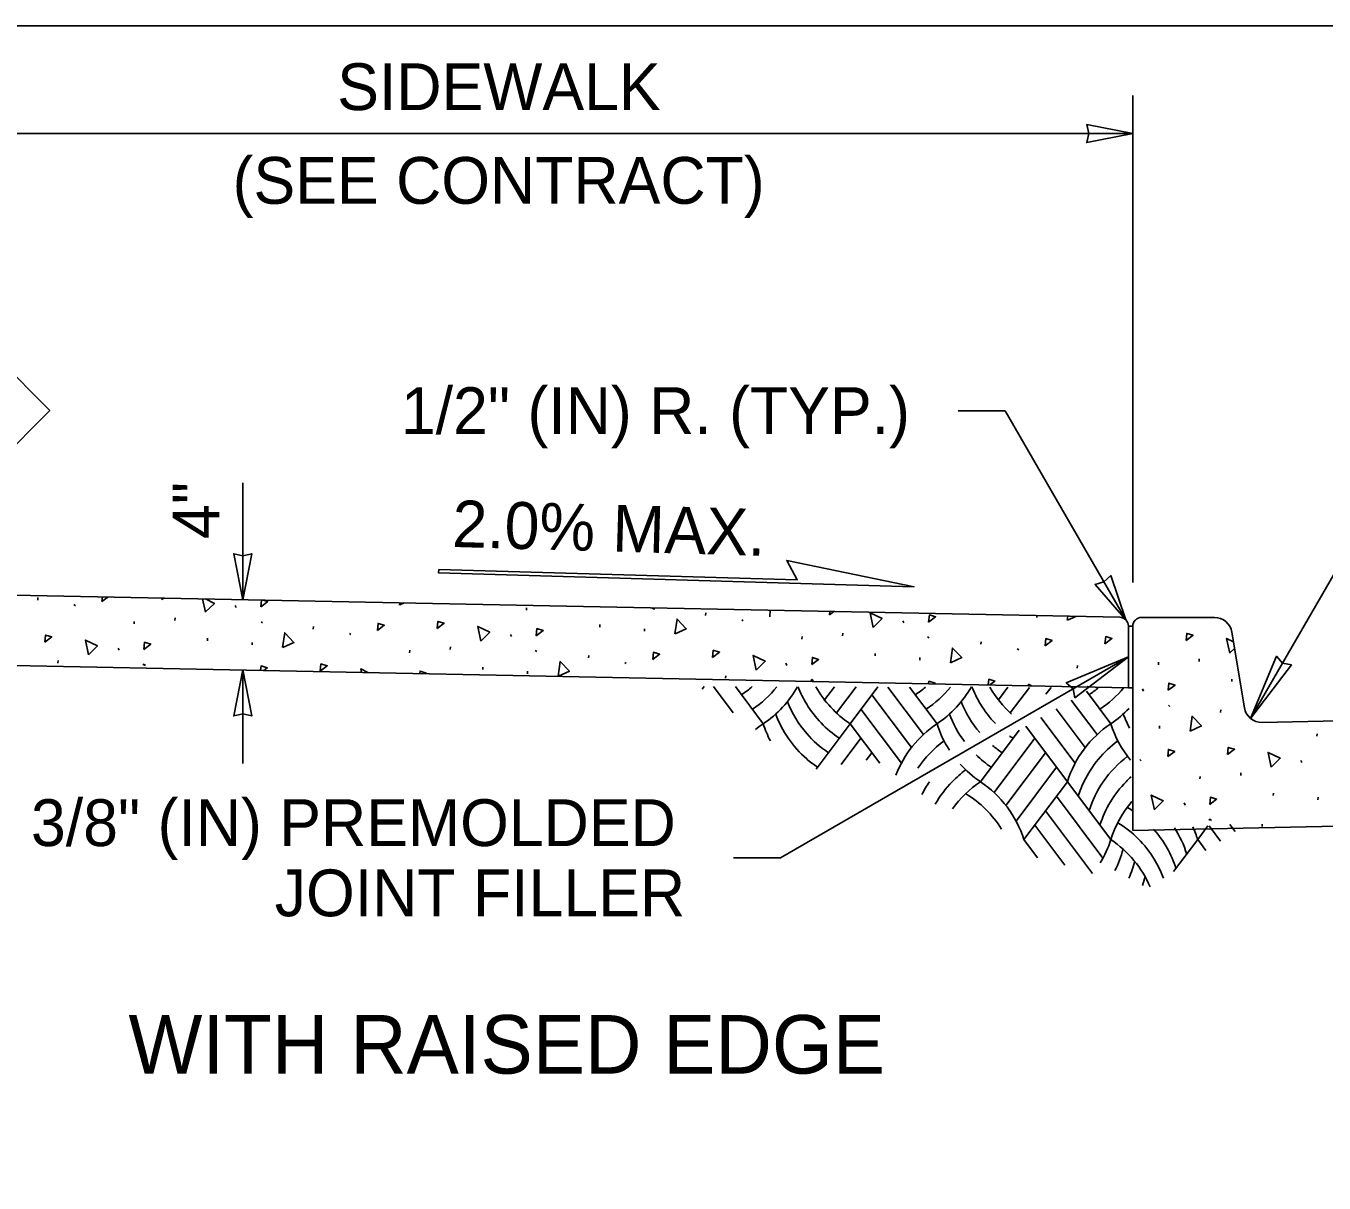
# Model space of a CAD drawing. Extents: x 99862 to 103151, y 100000 to 102076.
# Drawn here: x 100337.6 to 100781.3, y 101680 to 102075.5 of the extents above; entities that cross this region are included whole.
import ezdxf

# ---------------------------------------------------------------- set-up
doc = ezdxf.new("R2010")
doc.units = 0
for name, color, linetype in [('Level 1', 7, 'Continuous'), ('Level 13', 7, 'Continuous'), ('Level 15', 7, 'Continuous'), ('Level 16', 7, 'Continuous'), ('Level 20', 7, 'Continuous'), ('Level 34', 7, 'Continuous'), ('Level 6', 7, 'Continuous')]:
    doc.layers.add(name, color=color, linetype=linetype)

msp = doc.modelspace()

# ---------------------------------------------------------------- linework, layer by layer
at = {"layer": 'Level 1'}
msp.add_lwpolyline([(99862, 99999.5), (103151, 99999.5), (103151, 102075.5), (99862, 102075.5)], close=True, dxfattribs=at)
at = {"layer": 'Level 13'}
for p, q in [((100341.62, 101879.25), (100341.68, 101880.12)), ((100353.99, 101877.7), (100354.51, 101877.32)), ((100409.07, 101877.42), (100409.43, 101876.7)), ((100454.83, 101878.48), (100454.83, 101878.51)), ((100508.65, 101875.77), (100508.71, 101876.64)), ((100522.57, 101876.96), (100522.59, 101877.16)), ((100551.64, 101876.57), (100552.15, 101876.2)), ((100552.04, 101876.51), (100552.55, 101876.13)), ((100374.54, 101871.1), (100374.6, 101871.97)), ((100388.47, 101872.3), (100388.53, 101873.17)), ((100417.93, 101871.84), (100418.45, 101871.46)), ((100569.85, 101874.03), (100569.91, 101874.9)), ((100582.23, 101872.49), (100582.74, 101872.11)), ((100637.31, 101872.21), (100637.67, 101871.49)), ((100683.06, 101873.27), (100683.11, 101873.95)), ((100435.75, 101869.37), (100435.81, 101870.24)), ((100448.12, 101867.82), (100448.64, 101867.44)), ((100503.2, 101867.54), (100503.56, 101866.82)), ((100533.69, 101870.05), (100533.75, 101870.92)), ((100548.96, 101868.6), (100549.02, 101869.47)), ((100616.71, 101867.08), (100616.77, 101867.95)), ((100399.59, 101865.38), (100399.65, 101866.25)), ((100414.86, 101863.93), (100414.92, 101864.81)), ((100482.6, 101862.42), (100482.66, 101863.29)), ((100602.78, 101865.89), (100602.84, 101866.76)), ((100645.76, 101866.7), (100646.28, 101866.32)), ((100663.99, 101864.15), (100664.05, 101865.02)), ((100348.5, 101857.75), (100348.56, 101858.62)), ((100369.1, 101862.87), (100369.46, 101862.15)), ((100468.67, 101861.22), (100468.73, 101862.09)), ((100511.66, 101862.03), (100512.18, 101861.65)), ((100529.88, 101859.48), (100529.94, 101860.36)), ((100627.82, 101860.17), (100627.88, 101861.04)), ((100643.09, 101858.72), (100643.15, 101859.59)), ((100676.36, 101862.61), (100676.88, 101862.23)), ((100738.57, 101858.31), (100738.63, 101859.18)), ((100377.56, 101857.36), (100378.07, 101856.98)), ((100377.96, 101857.29), (100378.48, 101856.92)), ((100493.72, 101855.5), (100493.78, 101856.37)), ((100508.99, 101854.05), (100509.05, 101854.92)), ((100542.26, 101857.94), (100542.77, 101857.56)), ((100597.34, 101857.66), (100597.69, 101856.94)), ((100696.91, 101856), (100696.97, 101856.88)), ((100710.84, 101857.2), (100710.9, 101858.07)), ((100724.64, 101857.12), (100724.7, 101857.99)), ((100576.73, 101852.53), (100576.79, 101853.41)), ((100605.79, 101852.15), (100606.31, 101851.77)), ((100606.2, 101852.08), (100606.71, 101851.7)), ((100749.69, 101851.4), (100749.75, 101852.27)), ((100719.2, 101848.89), (100719.56, 101848.17)), ((100728.06, 101843.31), (100728.58, 101842.93)), ((100745.88, 101840.83), (100745.94, 101841.7)), ((100724.99, 101835.4), (100725.05, 101836.27)), ((100778.8, 101832.69), (100778.86, 101833.56)), ((100718.28, 101824.74), (100718.8, 101824.36)), ((100773.36, 101824.46), (100773.72, 101823.74)), ((100738.83, 101818.14), (100738.89, 101819.01)), ((100752.76, 101819.33), (100752.82, 101820.2)), ((100733.39, 101809.91), (100733.75, 101809.19)), ((100763.88, 101812.42), (100763.94, 101813.29)), ((100779.15, 101810.97), (100779.21, 101811.84)), ((100741.85, 101804.4), (100742.36, 101804.02)), ((100742.25, 101804.33), (100742.77, 101803.95)), ((100760.07, 101801.85), (100760.13, 101802.72))]:
    msp.add_line(p, q, dxfattribs=at)
for points in [[(100363.54, 101878.72), (100363.7, 101880.33)], [(100365.6, 101880.3), (100363.54, 101878.72)], [(100384.01, 101879.42), (100384.06, 101879.93)], [(100384.66, 101879.91), (100384.01, 101879.42)], [(100398.94, 101875.13), (100397.97, 101879.65)], [(100398.91, 101879.63), (100401.97, 101878.14), (100399, 101875.19)], [(100417.87, 101876.95), (100418.1, 101879.25)], [(100418.66, 101879.23), (100420.24, 101878.76), (100417.87, 101876.95)], [(100465.28, 101877.56), (100465.38, 101878.3)], [(100466.83, 101878.27), (100465.36, 101877.59)], [(100478.14, 101869.53), (100478.38, 101871.98), (100480.51, 101871.34), (100478.14, 101869.53)], [(100559.41, 101867.68), (100560.11, 101872.75), (100563.29, 101869.47), (100559.49, 101867.71)], [(100591.78, 101873.51), (100592, 101875.77)], [(100612.24, 101874.2), (100612.36, 101875.36)], [(100613.73, 101875.33), (100612.24, 101874.2)], [(100627.17, 101869.91), (100626.1, 101874.92), (100630.21, 101872.92), (100627.24, 101869.97)], [(100646.11, 101871.73), (100646.35, 101874.18), (100648.47, 101873.54), (100646.11, 101871.73)], [(100693.51, 101872.34), (100693.71, 101873.73)], [(100696.41, 101873.68), (100693.6, 101872.38)], [(100425.3, 101863.01), (100426.01, 101868.09), (100429.19, 101864.8), (100425.39, 101863.04)], [(100457.68, 101868.84), (100457.92, 101871.29), (100460.04, 101870.65), (100457.68, 101868.84)], [(100493.07, 101865.25), (100491.99, 101870.26), (100496.11, 101868.26), (100493.14, 101865.3)], [(100512, 101867.07), (100512.24, 101869.52), (100514.37, 101868.87), (100512, 101867.07)], [(100734.11, 101865.43), (100734.35, 101867.88), (100736.48, 101867.24), (100734.11, 101865.43)], [(100344.04, 101864.87), (100344.28, 101867.32), (100346.4, 101866.67), (100344.04, 101864.87)], [(100358.96, 101860.58), (100357.89, 101865.59), (100362, 101863.59), (100359.03, 101860.64)], [(100377.9, 101862.4), (100378.14, 101864.85), (100380.26, 101864.21), (100377.9, 101862.4)], [(100685.91, 101863.62), (100686.15, 101866.08), (100688.28, 101865.43), (100685.91, 101863.62)], [(100706.38, 101864.32), (100706.62, 101866.77), (100708.74, 101866.12), (100706.38, 101864.32)], [(100715.89, 101866.58), (100716.01, 101866.54), (100715.89, 101866.45)], [(100749.04, 101861.14), (100747.96, 101866.15), (100750.27, 101865.03)], [(100551.81, 101858.96), (100552.05, 101861.41), (100554.17, 101860.76), (100551.81, 101858.96)], [(100572.27, 101859.65), (100572.51, 101862.1), (100574.64, 101861.46), (100572.27, 101859.65)], [(100587.2, 101855.36), (100586.13, 101860.37), (100590.24, 101858.38), (100587.27, 101855.42)], [(100606.13, 101857.19), (100606.38, 101859.64), (100608.5, 101858.99), (100606.13, 101857.19)], [(100653.54, 101857.8), (100654.24, 101862.87), (100657.42, 101859.59), (100653.62, 101857.83)], [(100750.65, 101862.74), (100749.11, 101861.2)], [(100417.8, 101855.25), (100417.95, 101856.74), (100420.07, 101856.1), (100418.93, 101855.23)], [(100438.17, 101854.99), (100438.41, 101857.44), (100440.53, 101856.79), (100438.17, 101854.99)], [(100452.27, 101854.56), (100452.02, 101855.71), (100454.47, 101854.52)], [(100472.19, 101854.16), (100472.27, 101854.97), (100474.4, 101854.33), (100474.13, 101854.12)], [(100519.45, 101853.22), (100520.14, 101858.21), (100523.32, 101854.92), (100519.64, 101853.21)], [(100646.1, 101850.69), (100646.18, 101851.53), (100648.31, 101850.88), (100648, 101850.65)], [(100666.45, 101850.28), (100666.65, 101852.22), (100668.77, 101851.58), (100667.06, 101850.27)], [(100680.36, 101850), (100680.26, 101850.49), (100681.31, 101849.98)], [(100700.49, 101849.6), (100700.51, 101849.75), (100701.06, 101849.59)], [(100728, 101848.42), (100728.24, 101850.87), (100730.37, 101850.22), (100728, 101848.42)], [(100735.44, 101834.48), (100736.14, 101839.55), (100739.32, 101836.27), (100735.52, 101834.51)], [(100727.83, 101825.76), (100728.08, 101828.21), (100730.2, 101827.56), (100727.83, 101825.76)], [(100748.3, 101826.45), (100748.54, 101828.9), (100750.66, 101828.26), (100748.3, 101826.45)], [(100763.23, 101822.16), (100762.15, 101827.17), (100766.26, 101825.18), (100763.29, 101822.22)], [(100723.25, 101807.61), (100722.18, 101812.63), (100726.29, 101810.63), (100723.32, 101807.67)], [(100742.19, 101809.44), (100742.43, 101811.89), (100744.55, 101811.24), (100742.19, 101809.44)]]:
    msp.add_lwpolyline(points, dxfattribs=at)
at = {"layer": 'Level 15'}
for p, q in [((100715.89, 101885.32), (100715.89, 102051.71)), ((100284.64, 102038.71), (100715.89, 102038.71)), ((100672.24, 101944), (100656.24, 101944)), ((100713.53, 101872.48), (100672.24, 101944)), ((100756.12, 101838.81), (100806.01, 101925.21)), ((100411.69, 101879.37), (100411.69, 101919.37)), ((100714.39, 101859.85), (100595.45, 101791.18)), ((100411.69, 101855.37), (100411.69, 101823.37)), ((100579.45, 101791.18), (100595.45, 101791.18))]:
    msp.add_line(p, q, dxfattribs=at)
for points in [[(100715.89, 102038.71), (100700.16, 102041.8), (100700.89, 102038.71), (100700.16, 102035.63)], [(100411.68, 101879.37), (100414.77, 101895.1), (100411.68, 101894.37), (100408.6, 101895.1)], [(100713.53, 101872.48), (100703, 101884.56), (100706.03, 101885.47), (100708.34, 101887.64)], [(100714.39, 101859.85), (100696.11, 101845.85), (100695.53, 101848.96), (100693.13, 101851.02)], [(100756.12, 101838.81), (100770.12, 101857.08), (100767.01, 101857.66), (100764.95, 101860.07)], [(100411.68, 101855.37), (100408.6, 101839.65), (100411.68, 101840.38), (100414.77, 101839.65)]]:
    msp.add_lwpolyline(points, close=True, dxfattribs=at)
at = {"layer": 'Level 16'}
msp.add_lwpolyline([(100714.39, 101870.32), (100715.89, 101870.32), (100715.89, 101849.32), (100714.39, 101849.32)], close=True, dxfattribs=at)
at = {"layer": 'Level 20'}
for points in [[(100328.17, 101961.66), (100345.73, 101944.11), (100328.17, 101926.56), (100310.62, 101944.11)], [(100478.66, 101889.76), (100601.18, 101886.21), (100597.63, 101892.8), (100641.14, 101883.82), (100478.63, 101888.52)]]:
    msp.add_lwpolyline(points, close=True, dxfattribs=at)
at = {"layer": 'Level 34'}
for p, q in [((100568.72, 101848.77), (100569.44, 101849.73)), ((100572.6, 101849.72), (100579.35, 101840.71)), ((100580.04, 101849.7), (100589.58, 101836.98)), ((100610.54, 101845.13), (100613.89, 101849.6)), ((100614.62, 101840.67), (100621.3, 101849.58)), ((100619.27, 101836.98), (100628.71, 101849.56)), ((100626.7, 101846.88), (100640.24, 101828.82)), ((100632.12, 101849.55), (100644.32, 101833.28)), ((100639.56, 101849.53), (100648.97, 101836.98)), ((100669.94, 101845.13), (100673.16, 101849.44)), ((100674.02, 101840.67), (100680.57, 101849.41)), ((100686.22, 101847.05), (100687.98, 101849.39)), ((100700.03, 101848.09), (100708.37, 101836.98)), ((100622.99, 101841.93), (100636.8, 101823.51)), ((100689.67, 101842.11), (100699.64, 101828.82)), ((100694.85, 101845.1), (100703.71, 101833.28)), ((100607.68, 101821.52), (100619.27, 101836.98)), ((100619.27, 101836.98), (100629.38, 101823.5)), ((100684.49, 101839.12), (100696.19, 101823.51)), ((100616.24, 101823.03), (100622.99, 101832.03)), ((100663.82, 101817.18), (100677.06, 101834.83)), ((100668.47, 101813.48), (100682.38, 101832.03)), ((100679.31, 101836.13), (100693.52, 101817.18)), ((100624.79, 101824.54), (100626.7, 101827.08)), ((100672.55, 101809.02), (100686.09, 101827.08)), ((100675.99, 101803.71), (100689.81, 101822.13)), ((100678.67, 101797.38), (100693.52, 101817.18)), ((100693.52, 101817.18), (100708.37, 101797.38)), ((100689.81, 101812.23), (100705.7, 101791.05)), ((100686.1, 101807.28), (100702.16, 101785.86)), ((100682.38, 101802.33), (100692.65, 101788.65)), ((100738.07, 101797.38), (100741.58, 101802.06)), ((100741.96, 101802.08), (100745.85, 101796.89)), ((100749.07, 101802.5), (100750.84, 101800.15)), ((100678.67, 101797.38), (100683.36, 101791.13)), ((100729.85, 101786.43), (100738.07, 101797.38)), ((100738.07, 101797.38), (100740.87, 101793.64))]:
    msp.add_line(p, q, dxfattribs=at)
for centre, start, end in [((100561.19, 101878.07), 303.9036, 310.9439), ((100564.9, 101873.12), 303.9036, 321.3719), ((100568.62, 101868.17), 303.9036, 330.4575), ((100636.52, 101863.22), 201.1838, 211.332), ((100640.23, 101868.17), 209.5732, 236.0964), ((100628.01, 101868.17), 303.9036, 330.4575), ((100695.92, 101863.22), 201.1838, 211.332), ((100620.59, 101878.07), 303.9036, 310.555), ((100624.3, 101873.12), 303.9036, 321.046), ((100699.63, 101868.17), 209.8669, 227.9552), ((100679.98, 101878.07), 303.9036, 310.1631), ((100683.69, 101873.12), 303.9036, 320.7185), ((100632.81, 101858.27), 201.4344, 220.9416), ((100636.52, 101863.22), 211.3319, 236.0964), ((100692.21, 101858.27), 201.4344, 220.3049), ((100695.92, 101863.22), 211.3319, 224.0978), ((100687.41, 101868.17), 303.9036, 316.375), ((100610.54, 101805.79), 123.9036, 128.9978), ((100625.39, 101848.37), 197.6434, 207.3316), ((100629.1, 101853.32), 200.2432, 228.9599), ((100669.93, 101805.79), 123.9036, 158.7251), ((100684.78, 101848.37), 197.6434, 212.8399), ((100688.5, 101853.32), 200.2432, 216.5579), ((100729.33, 101805.79), 123.9036, 162.3566), ((100744.18, 101848.37), 197.6434, 219.4329), ((100747.89, 101853.32), 200.2432, 208.3401), ((100632.81, 101858.27), 220.9415, 236.0964), ((100695.92, 101863.22), 233.7814, 236.0964), ((100614.25, 101800.84), 126.3063, 126.3124), ((100673.64, 101800.84), 126.3063, 146.1546), ((100692.21, 101858.27), 229.7898, 236.0964), ((100733.04, 101800.84), 126.3063, 154.2266), ((100629.1, 101853.32), 228.9599, 236.0964), ((100684.78, 101848.37), 222.0764, 236.0964), ((100688.5, 101853.32), 225.8952, 236.0937), ((100736.75, 101795.89), 127.1006, 145.4911), ((100681.07, 101790.94), 126.331, 135.7128), ((100740.47, 101790.94), 131.9878, 135.7128), ((100677.36, 101795.89), 145.491, 153.1583), ((100681.07, 101790.94), 135.7127, 150.412), ((100684.78, 101785.99), 123.9036, 144.3827), ((100642.86, 101785.99), 17.6434, 56.0963), ((100733.04, 101800.84), 154.2265, 162.3566), ((100736.75, 101795.89), 145.491, 162.3566), ((100740.47, 101790.94), 135.7127, 162.3566), ((100639.15, 101781.04), 31.9702, 58.5465), ((100744.18, 101785.99), 139.5359, 162.3566), ((100694.83, 101776.09), 56.3005, 59.3021), ((100691.12, 101771.14), 31.3316, 58.4874), ((100694.83, 101776.09), 40.9413, 41.4405), ((100698.54, 101781.04), 17.6434, 32.7769), ((100702.26, 101785.99), 17.6434, 24.8009), ((100672.56, 101808.77), 329.029, 342.3566), ((100687.41, 101766.19), 23.5442, 56.0964), ((100694.83, 101776.09), 17.6434, 40.9414), ((100676.27, 101803.82), 333.0258, 345.0113), ((100679.98, 101798.87), 337.028, 346.3199), ((100691.12, 101771.14), 20.2605, 31.3317), ((100683.69, 101793.92), 341.0553, 345.7713)]:
    msp.add_arc(centre, 37.58, start, end, dxfattribs=at)
at = {"layer": 'Level 6'}
for p, q in [((100711.45, 101873.38), (100289.84, 101881.81)), ((100718.89, 101873.32), (100743.81, 101873.32)), ((100714.39, 101849.32), (100714.39, 101870.38)), ((100715.89, 101800.54), (100715.89, 101870.32)), ((100749.73, 101868.31), (100754.04, 101842.44)), ((100714.39, 101849.32), (100248.65, 101858.63)), ((100820.83, 101838.64), (100760.08, 101837.42)), ((100823.89, 101802.7), (100715.89, 101800.54))]:
    msp.add_line(p, q, dxfattribs=at)
for centre, radius, start, end in [((100711.39, 101870.38), 3, 360, 88.8542), ((100718.89, 101870.32), 3, 90, 180), ((100743.81, 101867.32), 6, 9.4623, 90), ((100759.96, 101843.42), 6, 189.4623, 271.1458)]:
    msp.add_arc(centre, radius, start, end, dxfattribs=at)

# ---------------------------------------------------------------- texts
at = {"layer": 'Level 20'}
for s, height, p in [('SIDEWALK', 16, (100443.96, 102046.73)), ('(SEE CONTRACT)', 16, (100408.21, 102014.71)), ('1/2" (IN) R. (TYP.)', 16, (100465.71, 101936)), (' 3/8" (IN) PREMOLDED', 16, (100333.34, 101795.18)), ('JOINT FILLER', 16, (100422.61, 101771.18)), (' WITH RAISED EDGE', 20, (100365.19, 101717.41))]:
    msp.add_text(s, height=height, dxfattribs=at).set_placement(p)
for s, rotation, p in [('4"', 90, (100403.69, 101900.16)), ('2.0% MAX.', 358.3445, (100483.14, 101897.43))]:
    msp.add_text(s, height=16, rotation=rotation, dxfattribs=at).set_placement(p)

doc.saveas('drawing.dxf')
